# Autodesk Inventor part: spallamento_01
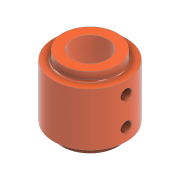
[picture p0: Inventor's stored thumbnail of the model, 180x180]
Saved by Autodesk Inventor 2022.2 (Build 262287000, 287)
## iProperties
Created: 2025-03
Part Number: spallamento_01
Material: Generico
Document SubType Name: Modeling
Designer: 18907419
Density: 1 g/cm^3
Appearance: Liscia - Arancione chiaro
Author: 18907419
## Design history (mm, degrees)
sketch "Schizzo1"
  geometry: L1 (-10.6, 150)-(10.6, 150) reference; L2 (10.6, 110)-(-10.6, 110) reference; L3 (0, 150)-(0, 110); L4 (10, 0)-(10, 200) reference; L5 (10.6, 150)-(15.6, 150); L6 (15.6, 150)-(15.6, 145); L7 (15.6, 145)-(20.6, 145); L8 (0, 130)-(39.125, 130); L9 (20.6, 145)-(20.6, 130); L10 (-10.6, 110)-(10.6, 110); L11 (10, 260)-(10, 60); L12 (10.6, 110)-(15.6, 110); L13 (15.6, 110)-(15.6, 115); L14 (15.6, 115)-(20.6, 115); L15 (20.6, 115)-(20.6, 130); L16 (10.6, 150)-(10, 150); L17 (10.6, 110)-(10, 110); 3 further points
  constraints: 30 end point, 5 point on line, 5 symmetric about line, 3 midpoint, 1 vertical, 2 other
  dimensions: "d0" = 5 distance of L1.end L5.end; "d1" = 5 distance of L5.end L6.end; "d2" = 5 distance of L6.end L7.end
revolve "Rivoluzione1" sketch "Schizzo1" stored, may be unused: angle "d3" = 90 deg
fillet "Raccordo1" dims "d4" = 1
sketch "Schizzo2"
  geometry: L1 (150, 15.6)-(150, -15.6) reference; L2 (110, 15.6)-(110, -15.6) reference; 3 further points
  dimensions: "d12" = 12 distance from line of L1 point (138, 0); "d13" = 12 distance from line of L2 point (122, 0)
hole "Foro1" sketch "Schizzo2" at (138, 0), (122, 0) diameter "d5" = 3.4; stored, may be unused: countersink angle "d9" = 90 deg, drill point angle "d11" = 118 deg; dims "d6" = 6, "d7" = 10.4, "d8" = 2, "d10" = 8
node "Piano di lavoro1"
sketch "Schizzo3"
  geometry: C1 r 1.7 at (-8, 0); C2 r 1.7 at (8, 0); 3 further points
  constraints: 2 centre point, 2 other
  dimensions: "d14" = 3.4 diameter of C2
hole "Foro2" sketch "Schizzo3" at (8, 0), (-8, 0) diameter "d15" = 3.4; stored, may be unused: countersink angle "d19" = 90 deg, drill point angle "d21" = 118 deg; dims "d16" = 6, "d17" = 6, "d18" = 5, "d20" = 8
mirror "Specchio1"
node "Solido1"
node "Riferimento1"
node "Riferimento2"
